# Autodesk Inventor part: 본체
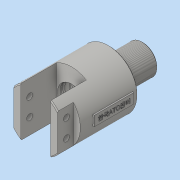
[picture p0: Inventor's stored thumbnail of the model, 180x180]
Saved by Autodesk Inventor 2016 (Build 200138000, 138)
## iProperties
Created: 2019-02
Part Number: 본체
Material: 일반
Document SubType Name: Modeling
Designer: 3sil_cad018
Density: 1 g/cm^3
Appearance: 기본값
Author: 3sil_cad018
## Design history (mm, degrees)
sketch "스케치1"
  geometry: C1 r 29 at (0, 0); 1 further point
  constraints: 1 centre point, 1 coincident
  dimensions: "d0" = 58 diameter of C1
extrude "돌출1" new body sketch "스케치1" stored distance "d1" = 74; taper "d2" = 0 deg
sketch "스케치2"
  geometry: C1 r 13 at (0, 0); 1 further point
  constraints: 1 centre point, 1 coincident
  dimensions: "d3" = 26 diameter of C1
extrude "돌출2" join sketch "스케치2" distance "d4" = 5; taper "d5" = 0 deg
sketch "스케치3"
  geometry: C1 r 15 at (0, 0); 1 further point
  constraints: 1 centre point, 1 coincident
  dimensions: "d6" = 30 diameter of C1
extrude "돌출3" join sketch "스케치3" distance "d7" = 29; taper "d8" = 0 deg
sketch "스케치4"
  geometry: L1 (29, 37)-(-29, 37) reference; L2 (0, -92.6)-(0, 58.6) reference; L3 (-15, 37)-(15, 37); L4 (15, 37)-(15, 1); L5 (15, 1)-(-15, 1); L6 (-15, 1)-(-15, 37); 2 further points
  constraints: 8 end point, 2 parallel, 1 horizontal, 1 midpoint, 1 perpendicular, 1 point on line, 1 vertical alignment
  dimensions: "d9" = 36 distance of L3.end L4.end; "d10" = 30 distance of L4.end L5.end
extrude "돌출4" cut sketch "스케치4" stored distance "d11" = 29; taper "d12" = 0 deg
sketch "스케치5"
  geometry: L1 (-15, 37)-(-29, 37) reference; L2 (29, 37)-(15, 37) reference; L3 (-29, 37)-(-22, 37); L4 (-22, 37)-(-22, 21); L5 (-22, 21)-(-29, 21); L6 (-29, 21)-(-29, 37); L7 (-15, 37)-(-15, 1) reference; 1 further point
  constraints: 8 end point, 2 parallel, 1 horizontal, 1 perpendicular
  dimensions: "d13" = 16 distance of L5.end L1.end; "d14" = 7 distance between parallel lines of L4 L7
extrude "돌출5" cut sketch "스케치5" stored distance "d15" = 29; taper "d16" = 0 deg
sketch "스케치6"
  geometry: L1 (-16, 0)-(-16, 37.789) reference; L2 (0, 0)-(0, 37.789) reference; L3 (-16, 37.789)-(-16, 0) reference; L4 (-16, 18.894)-(0, 18.894); L5 (0, 37.789)-(0, 0) reference; 3 further points
  constraints: 2 end point, 2 midpoint, 1 symmetric about line
  dimensions: "d17" = 18 distance of point (-7, 9.894) point (-7, 27.894); "d18" = 9 distance from line of L1 point (-7, 9.894)
hole "구멍1" sketch "스케치6" at (-7, 27.894), (-7, 9.894) diameter "d19" = 6; stored, may be unused: countersink angle "d23" = 90 deg, drill point angle "d25" = 118 deg; dims "d20" = 6, "d21" = 4, "d22" = 2, "d24" = 8
node "작업 평면1"
sketch "스케치7"
  geometry: L1 (5, 8)-(-5, 8); L2 (-5, 8)-(-5, -32); L3 (-5, -32)-(5, -32); L4 (5, -32)-(5, 8); L5 (-29, -37)-(29, -37) reference; 2 further points
  constraints: 8 end point, 2 parallel, 1 horizontal, 1 midpoint, 1 perpendicular, 1 vertical alignment
  dimensions: "d27" = 40 distance of L1.end L2.end; "d28" = 10 distance of L2.end L3.end; "d29" = 5 distance between parallel lines of L5 L3
extrude "돌출6" join sketch "스케치7" stored distance "d30" = 29; taper "d31" = 0 deg
sketch "스케치8"
  geometry: L1 (-8, -5)-(32, -5) reference; L2 (-8, 5)-(-8, -5) reference; 2 further points
  constraints: 1 other
  dimensions: "d32" = 5 distance from line of L1 point (12, 0); "d33" = 20 distance from line of L2 point (12, 0)
feature "엠보싱1" sketch "스케치8" dims "d9" = 36, "d10" = 30, "d34" = 0.5, "d35" = 0
sketch "스케치9"
  geometry: L1 (-15, 1)-(15, 1) reference; L2 (-15, -71)-(15, -71) reference; L3 (0, 1)-(0, -71); L4 (0, 1)-(14, 1); L5 (14, 1)-(14, -1.65); L6 (14, -1.65)-(0, -1.65); L7 (0, -1.65)-(0, 1); L8 (0, -1.65)-(17, -1.65); L9 (17, -1.65)-(17, -6.35); L10 (17, -6.35)-(0, -6.35); L11 (0, -6.35)-(0, -1.65); L12 (0, -6.35)-(14, -6.35); L13 (14, -6.35)-(14, -10.65); L14 (14, -10.65)-(0, -10.65); L15 (0, -10.65)-(0, -6.35); L16 (0, -10.65)-(17, -10.65); L17 (17, -10.65)-(17, -15.35); L18 (17, -15.35)-(0, -15.35); L19 (0, -15.35)-(0, -10.65); L20 (0, -15.35)-(14, -15.35); L21 (14, -15.35)-(14, -19); L22 (14, -19)-(0, -19); L23 (0, -19)-(0, -15.35); L24 (0, -19)-(16, -19); L25 (16, -19)-(16, -26); L26 (16, -26)-(0, -26); L27 (0, -26)-(0, -19); L28 (0, -26)-(4, -26); L29 (4, -26)-(4, -49); L30 (4, -49)-(0, -49); L31 (0, -49)-(0, -26); L32 (0, -49)-(7, -49); L33 (7, -49)-(7, -71); L34 (7, -71)-(0, -71); L35 (0, -71)-(0, -49); L36 (17, -4)-(0, -4); L37 (17, -13)-(0, -13); 1 further point
  constraints: 70 end point, 16 parallel, 8 horizontal, 8 perpendicular, 6 midpoint, 3 point on line, 1 collinear
  dimensions: "d36" = 5 distance between parallel lines of L36 L1; "d37" = 9 distance between parallel lines of L37 L36; "d38" = 27 distance between parallel lines of L26 L1; "d39" = 20 distance between parallel lines of L1 L22; "d40" = 4.7 distance of L8.end L9.end; "d41" = 4.7 distance of L16.end L17.end; "d42" = 22 distance of L32.end L33.end; "d43" = 14 diameter of L33 L3; "d44" = 8 diameter of L29 L3; "d45" = 28 diameter of L5 L3; "d46" = 34 diameter of L9 L3; "d47" = 32 diameter of L25 L3; "d48" = 7 distance of L24.end L25.end (derived)
revolve "회전1" sketch "스케치9" stored, may be unused: angle "d49" = 90 deg
feature "스레드1" dims "d50" = 10, "d51" = 0
feature "스레드2" dims "d52" = 18, "d53" = 0
fillet "모깎기1" dims "d54" = 0.8
chamfer "모따기1" distance "d55" = 1; stored, may be unused: second distance "d56" = 2, angle "d57" = 45 deg
chamfer "모따기2" distance "d58" = 1; stored, may be unused: second distance "d59" = 2, angle "d60" = 45 deg
node "솔리드1"
mirror "대칭1"
